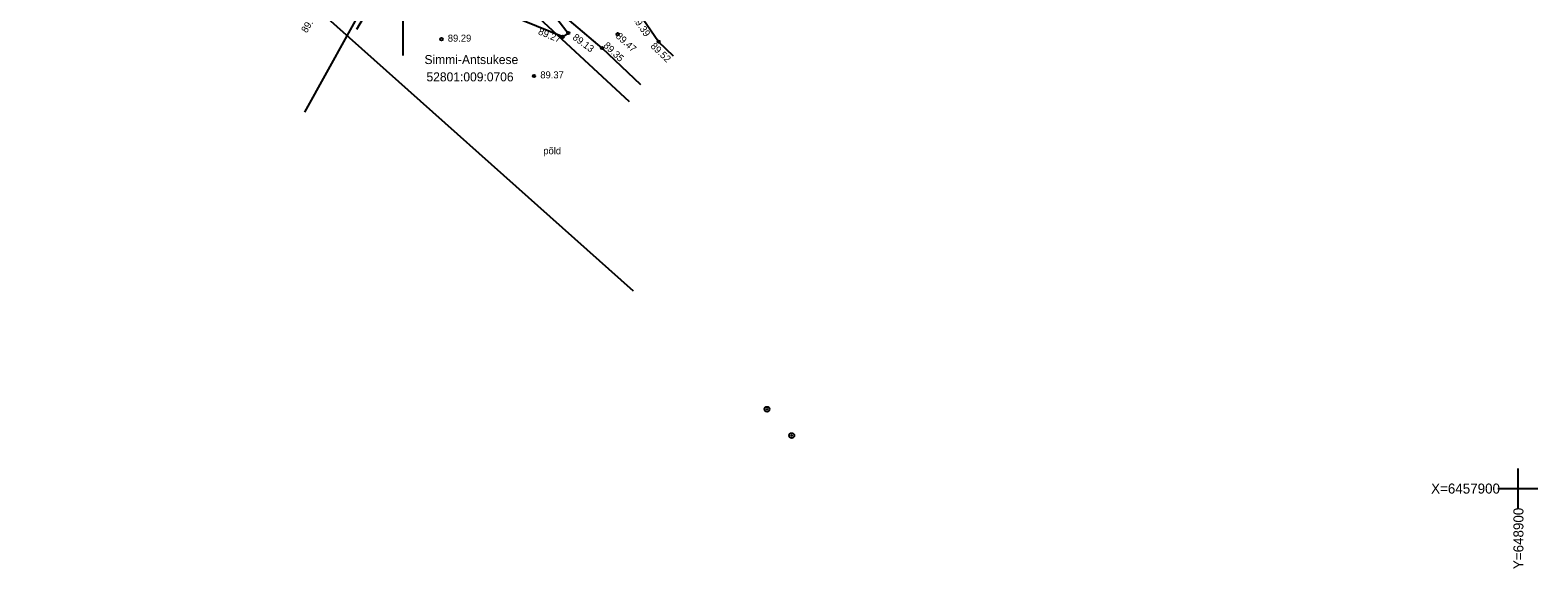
# Model space of a CAD drawing. Extents: x 648748 to 649126, y 6457789 to 6458252.
# Drawn here: x 648751.4 to 648902, y 6457892 to 6457945.8 of the extents above; entities that cross this region are included whole.
import ezdxf

# ---------------------------------------------------------------- set-up
doc = ezdxf.new("R2010")
doc.units = 0
for name, color, linetype in [('DTRASS', 7, 'Continuous'), ('HALJASTUS', 7, 'Continuous'), ('KORGUS-EH2000', 7, 'Continuous'), ('KPOHULIIN', 7, 'Continuous'), ('PIIR', 7, 'Continuous'), ('POST', 7, 'Continuous'), ('TEE', 7, 'Continuous'), ('VEEKOGU', 7, 'Continuous'), ('VORK', 7, 'Continuous')]:
    doc.layers.add(name, color=color, linetype=linetype)

msp = doc.modelspace()

# ---------------------------------------------------------------- linework, layer by layer
at = {"layer": 'DTRASS'}
msp.add_line((648788.64, 6457953.61), (648788.64, 6457943.27), dxfattribs=at)
at = {"layer": 'KORGUS-EH2000'}
for centre in [(648805.16, 6457945.52), (648792.5, 6457944.9), (648804.61, 6457945.14), (648808.54, 6457944.02), (648810.09, 6457945.4), (648814.18, 6457944.65), (648801.74, 6457941.23)]:
    msp.add_circle(centre, 0.125, dxfattribs=at)
at = {"layer": 'KPOHULIIN'}
msp.add_line((648751.42, 6457973.56), (648811.64, 6457919.76), dxfattribs=at)
at = {"layer": 'PIIR'}
for p, q in [((648778.84, 6457937.61), (648786.87, 6457952.13)), ((648800.9, 6457948.28), (648811.26, 6457938.68))]:
    msp.add_line(p, q, dxfattribs=at)
at = {"layer": 'POST'}
for centre, radius in [((648825.01, 6457907.94), 0.25), ((648825.01, 6457907.94), 0.0234), ((648827.48, 6457905.31), 0.25), ((648827.48, 6457905.31), 0.0234)]:
    msp.add_circle(centre, radius, dxfattribs=at)
at = {"layer": 'TEE'}
for points in [[(648812.41, 6457940.36), (648808.54, 6457944.02), (648800.05, 6457951.25), (648791.29, 6457958.01), (648789.24, 6457958.44), (648786.75, 6457957.52), (648784.75, 6457956.72)], [(648815.68, 6457943.21), (648814.18, 6457944.65), (648812.26, 6457947.42), (648811.63, 6457949.95)]]:
    msp.add_lwpolyline(points, dxfattribs=at)
at = {"layer": 'VEEKOGU'}
msp.add_lwpolyline([(648781.55, 6457947.52), (648782.64, 6457949.28), (648785.59, 6457954.34), (648789.76, 6457953.43), (648797.17, 6457950.22), (648804.11, 6457946.85), (648805.16, 6457945.52), (648804.61, 6457945.14), (648796.89, 6457948.27), (648788.55, 6457951.04), (648787.17, 6457950.82), (648785.34, 6457948.14), (648784.01, 6457945.88)], dxfattribs=at)
at = {"layer": 'VORK'}
for p, q in [((648900, 6457902), (648900, 6457898)), ((648898, 6457900), (648902, 6457900))]:
    msp.add_line(p, q, dxfattribs=at)

# ---------------------------------------------------------------- texts
at = {"layer": 'HALJASTUS'}
msp.add_text('põld', height=0.7, dxfattribs=at).set_placement((648802.67, 6457933.41))
at = {"layer": 'KORGUS-EH2000'}
for s, rotation, p in [(' 89.08', 58.9436, (648778.9, 6457945.25)), (' 89.39', 304.6403, (648811.36, 6457947.22)), (' 89.27', 337.9562, (648801.85, 6457945.51)), (' 89.13', 323.1568, (648805.32, 6457945.11)), (' 89.35', 316.5396, (648808.43, 6457944.38)), (' 89.47', 317.2949, (648809.66, 6457945.3)), (' 89.52', 316.351, (648813.13, 6457944.32))]:
    msp.add_text(s, height=0.7, rotation=rotation, dxfattribs=at).set_placement(p)
for s, p in [(' 89.29', (648792.87, 6457944.66)), (' 89.37', (648802.11, 6457940.99))]:
    msp.add_text(s, height=0.7, dxfattribs=at).set_placement(p)
at = {"layer": 'PIIR'}
for s, p in [('Simmi-Antsukese', (648790.8, 6457942.42)), ('52801:009:0706', (648791, 6457940.69))]:
    msp.add_text(s, height=0.9, rotation=0, dxfattribs=at).set_placement(p)
at = {"layer": 'VORK'}
msp.add_text('X=6457900     ', height=1, dxfattribs=at).set_placement((648891.34, 6457899.51))
msp.add_text('Y=648900     ', height=1, rotation=90, dxfattribs=at).set_placement((648900.56, 6457891.96))

doc.saveas('drawing.dxf')
